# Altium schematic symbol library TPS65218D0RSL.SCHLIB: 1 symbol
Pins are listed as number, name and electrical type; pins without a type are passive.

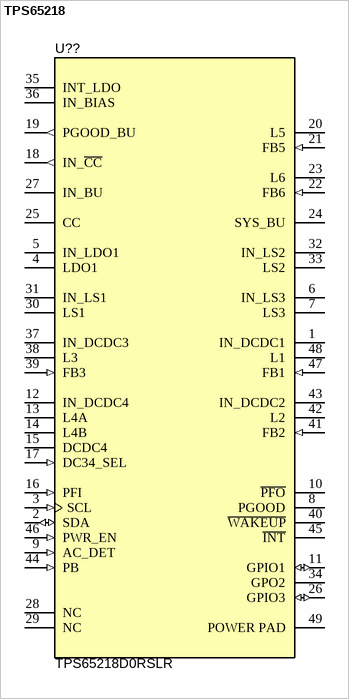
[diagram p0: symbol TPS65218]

## TPS65218
designator U??, comment TPS65218D0RSLR
Integrated Power Management (PMIC) for ARM® Cortex™-A8/A9 SOCs and FPGAs, RSL0048B (VQFN-48); Alternate PartNumber: TPS65218D0RSLT; Alternate Manufacturer: Texas Instruments; SizeAreaWB_mm2: 64; Rating: Catalog; SizeZ_mm: 1; SizeX_mm: 6; SizeArea_mm2: 36; CompType: IC; AEC Qualified: N; AEC Category: Q200
footprint RSL0048B
footprint RSL0048B_NV
pins: 1 IN_DCDC1 (power) "Input supply pin for DCDC1.", 2 SDA (io) "Data line for the I2C interface. Connect to pull-up resistor.", 3 SCL (in) "Clock input for the I2C interface.", 4 LDO1 (power) "Output voltage pin for LDO1. Connect to capacitor.", 5 IN_LDO1 (power) "Input supply pin for LDO1.", 6 IN_LS3 (power) "Input supply pin for load switch 3.", 7 LS3 (power) "Output voltage pin for load switch 3. Connect to capacitor.", 8 PGOOD (oc) "Power-good output (can be configured as open drain or push-pull). Pulled low when either DCDC1-4 or LDO1 are out of regulation. Load switches and DCDC5-6 do not affect PGOOD pin.", 9 AC_DET (in) "Power enable input for DCDC1-4, LDOs and load switches. See state diagram for details. Tie this pin to IN_BIAS if not used.", 10 ~{PFO} (oc) "Power-fail comparator output, deglitched (open drain). Pin is pulled low when PFI input is below power-fail threshold.", 11 GPIO1 (io) "Pin can be configured as DDR reset-input (driving GPO2) or as general-purpose, open-drain output.", 12 IN_DCDC4 (power) "Input supply pin for DCDC4.", 13 L4A (power) "Switch pin for DCDC4. Connect to inductor.", 14 L4B (power) "Switch pin for DCDC4. Connect to inductor.", 15 DCDC4 (power) "Output voltage pin for DCDC4. Connect to capacitor.", 16 PFI (in) "Power-Fail comparator input. Connect to resistor divider.", 17 DC34_SEL (in) "Power-up default selection pin for DCDC3 or DCDC4. Power-up default is programmed by a resistor connected to ground.", 18 IN_~{CC} (out) "Output pin indicating if DCDC5 and DCDC6 are powered from main supply (IN_BU) or coin-cell battery (CC).", 19 PGOOD_BU (out) "Power-good output (push/pull) for battery backup supplies. Pulled low when either DCDC5 or DCDC6 is out of regulation. Pulled high (to DCDC6 output voltage) when both rails are in regulation.", 20 L5 (power) "Switch pin for DCDC5. Connect to inductor.", 21 FB5 (in) "Feedback voltage pin for DCDC5. Connect to output capacitor.", 22 FB6 (in) "Feedback voltage pin for DCDC6. Connect to output capacitor.", 23 L6 (power) "Switch pin for DCDC6. Connect to inductor.", 24 SYS_BU (power) "System voltage pin for battery-backup supply power path. Connect to capacitor. Not recommended to connect any external load to this pin.", 25 CC (power) "Coin Cell battery input. Serves as the supply to DCDC5 and DCDC6 if no voltage is applied to IN_BU. Tie this pin to ground if not used.", 26 GPIO3 (io) "Pin can be configured as PMIC reset or general-purpose, open-drain output.", 27 IN_BU (power) "Default input supply pin for battery backup supplies (DCDC5 and DCDC6).", 28 NC "No connect. Leave pin floating.", 29 NC "No connect. Leave pin floating.", 30 LS1 (power) "Output voltage pin for load switch 1. Connect to capacitor.", 31 IN_LS1 (power) "Input supply pin for load switch 1.", 32 IN_LS2 (power) "Input supply pin for load switch 2.", 33 LS2 (power) "Output voltage pin for load switch 2. Connect to capacitor.", 34 GPO2 (oc) "Pin can be configured as DDR reset signal (controlled by GPIO1) or as general-purpose output. Buffer can be configured as push-pull or open-drain.", 35 INT_LDO (power) "Internal bias voltage. It is not recommended to connect any external load to this pin.", 36 IN_BIAS (power) "Input supply pin for reference system.", 37 IN_DCDC3 (power) "Input supply pin for DCDC3.", 38 L3 (power) "Switch pin for DCDC3. Connect to inductor.", 39 FB3 (in) "Feedback voltage pin for DCDC3. Connect to feedback resistor divider.", 40 ~{WAKEUP} (oc) "Signal to SOC to indicate a power on event (active low, open-drain output)", 41 FB2 (in) "Feedback voltage pin for DCDC2. Connect to output capacitor.", 42 L2 (power) "Switch pin for DCDC2. Connect to inductor.", 43 IN_DCDC2 (power) "Input supply pin for DCDC2.", 44 PB (in) "Push-button monitor input. Typically connected to a momentary switch to ground (active low). See state diagram for details.", 45 ~{INT} (oc) "Interrupt output (active low, open drain). Pin is pulled low if an interrupt bit is set. The returns to HiZ state after the bit causing the interrupt has been read. Interrupts can be masked.", 46 PWR_EN (in) "Power enable input for DCDC1-4, LDOs and load switches. See state diagram for details.", 47 FB1 (in) "Feedback voltage pin for DCDC1. Connect to output capacitor.", 48 L1 (power) "Switch pin for DCDC1. Connect to inductor.", 49 POWER PAD (power) "Power ground and thermal relief. Connect to ground plane."
1 alternate drawing of the same symbol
